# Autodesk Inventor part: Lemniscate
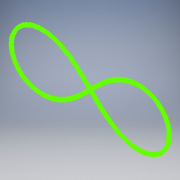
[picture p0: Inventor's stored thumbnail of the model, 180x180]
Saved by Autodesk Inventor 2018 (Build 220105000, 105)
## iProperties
Created: 2008-02
Part Number: Lemniscate
Document SubType Name: Modeling
Designer: Autodesk, Inc.
Density: 1 g/cm^3
Material: Generic
Appearance: Default
Author: Autodesk, Inc.
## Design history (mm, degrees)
sketch "Sketch1"
  geometry: 299 further points
  constraints: 299 other
